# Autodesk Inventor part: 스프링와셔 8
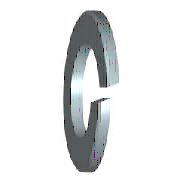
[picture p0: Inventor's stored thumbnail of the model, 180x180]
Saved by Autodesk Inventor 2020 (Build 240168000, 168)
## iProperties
Created: 2012-02
Part Number: 스프링와셔 8
Material: 강철, 연강
Description: 스프링 잠금 와셔
Document SubType Name: Modeling
Standard: KS B 1324
Designer: mduedu
Standards Organization: KS
Language: ko-KR
Size Designation: 번호 3 - 8
Categories: <MemberInstance><Categories><Category DisplayName="조임쇠" InternalName="e4da775c-781d-43d5-af7c-5136215cf5a6" Mnemonic="FSTN"><Category DisplayName="와셔" InternalN
Density: 1 g/cm^3
Appearance: 파란색 - 벽 페인트 - 광택
IsCustomPart: 1
Author: mduedu
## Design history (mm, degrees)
sketch "스케치1"
  geometry: C1 r 7.4 at (0, 0); C2 r 4.1 at (0, 0); 1 further point
  constraints: 2 centre point, 2 coincident
  dimensions: "d0" = 8.2 diameter of C2 (= SD1); "d1" = 14.8 diameter of C1 (= SD2)
extrude "본체" new body sketch "스케치1" distance "d2" = 2.5 (= SD); taper "d3" = 0 deg
sketch "스케치2"
  geometry: L1 (0, -4.1)-(0, 4.1) reference; L2 (2.5, 7.4)-(2.5, -7.4) reference; L3 (-1.2, 0)-(7.2, 0) reference; L4 (0, -0.5)-(2.5, 0.41); L5 (0, 0.5)-(2.5, 1.41)
  constraints: 4 end point, 4 point on line, 1 parallel
  dimensions: "d4" = 0.5 distance from line of L3 L4.start (= 0.2 x SD); "d5" = 0.5 distance from line of L3 L5.start (= 0.2 x SD); "d6" = 70 deg angle of L2 L4 (= FAWI)
extrude "절단부" cut sketch "스케치2" stored distance "d7" = 2.5 (= SD); taper "d8" = 0 deg
workaxis "Work Axis1"
workplane "Work Plane1"
body "Solid1"
other parameters: "SD1" = 8.2 [user parameter; used in 1 equation term], "SD2" = 14.8 [user parameter; used in 1 equation term], "SD" = 2.5 [user parameter; used in 4 equation terms], "FAWI" = 70 deg [user parameter; used in 1 equation term], "d9" = 0, "d10" = 0, "d11" = 0, "d12" = 0, "SDI" = 3.3 [user parameter], "NND" = 8 [user parameter]
